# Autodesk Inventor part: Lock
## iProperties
Created: 2009-03
Part Number: Lock
Document SubType Name: Modeling
Designer: tangg
Density: 7.84 g/cm^3
Material: Steel, High Strength Low Alloy
Mass: 9.0689 g
Surface Area: 17.998 cm^2
Volume: 1.15675 cm^3
Author: tangg
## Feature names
1. Extrusion1
2. Extrusion2
3. Chamfer1
